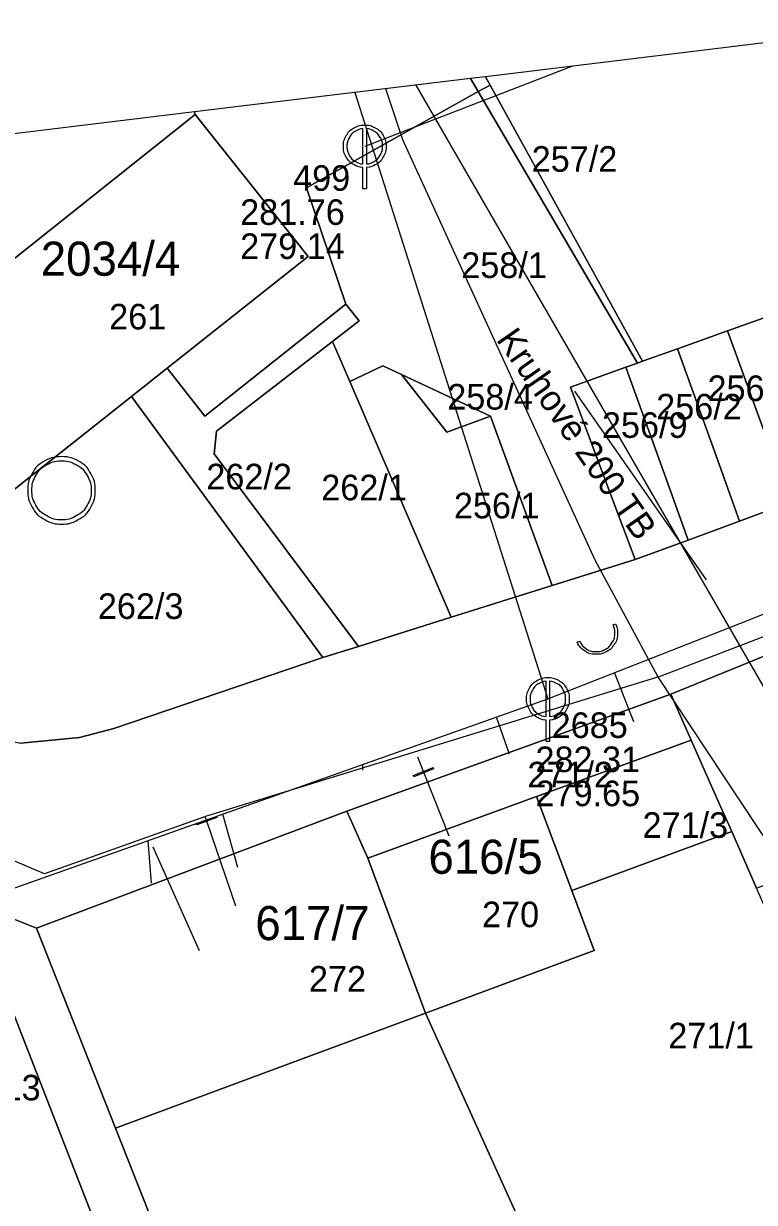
# Model space of a CAD drawing. Extents: x -571312 to -571060, y -1087128 to -1086933.
# Drawn here: x -571250.5 to -571207.6, y -1087007.2 to -1086938.1 of the extents above; entities that cross this region are included whole.
import ezdxf

# ---------------------------------------------------------------- set-up
doc = ezdxf.new("R2010")
doc.units = 0
for name, color, linetype in [('Adresní místo-text', 7, 'Continuous'), ('Armatura vodovodní', 7, 'Continuous'), ('Default', 7, 'Continuous'), ('Elektro NN - vedení', 7, 'Continuous'), ('Kanalizační přípojka', 7, 'Continuous'), ('Kanalizační stoka', 7, 'Continuous'), ('Kanalizační šachta', 7, 'Continuous'), ('Nepropojené křížení', 7, 'Continuous'), ('Parcela-polygon', 7, 'Continuous'), ('Parcela-text', 7, 'Continuous'), ('Popis kmenové stoky', 7, 'Continuous'), ('Popis šachty', 7, 'Continuous'), ('Vodovodní přípojka', 7, 'Continuous'), ('Vodovodní řad', 7, 'Continuous')]:
    doc.layers.add(name, color=color, linetype=linetype)

msp = doc.modelspace()

# ---------------------------------------------------------------- linework, layer by layer
at = {"layer": 'Armatura vodovodní'}
for points in [[(-571226.461, -1086981.776), (-571227.624, -1086982.236), (-571227.652, -1086982.163), (-571226.49, -1086981.703), (-571226.461, -1086981.776)], [(-571239.176, -1086984.632), (-571240.35, -1086985.063), (-571240.377, -1086984.989), (-571239.203, -1086984.559), (-571239.176, -1086984.632)]]:
    msp.add_lwpolyline(points, dxfattribs=at)
at = {"layer": 'Default'}
for points in [[(-571230.603, -1086946.508), (-571230.861, -1086946.49), (-571231.123, -1086946.344), (-571231.42, -1086946.18), (-571231.585, -1086945.883), (-571231.75, -1086945.585), (-571231.75, -1086945.26), (-571231.75, -1086944.933), (-571231.582, -1086944.633), (-571231.413, -1086944.332), (-571231.115, -1086944.171), (-571230.817, -1086944.01), (-571230.5, -1086944.01), (-571230.185, -1086944.01), (-571229.886, -1086944.171), (-571229.587, -1086944.332), (-571229.418, -1086944.633), (-571229.25, -1086944.933), (-571229.25, -1086945.26), (-571229.25, -1086945.585), (-571229.415, -1086945.883), (-571229.58, -1086946.18), (-571229.877, -1086946.344), (-571230.139, -1086946.49), (-571230.397, -1086946.508)], [(-571230.603, -1086944.222), (-571230.8, -1086944.239), (-571231.015, -1086944.354), (-571231.264, -1086944.489), (-571231.403, -1086944.739), (-571231.542, -1086944.989), (-571231.542, -1086945.26), (-571231.542, -1086945.531), (-571231.406, -1086945.778), (-571231.269, -1086946.024), (-571231.02, -1086946.161), (-571230.808, -1086946.281), (-571230.603, -1086946.295)], [(-571230.397, -1086946.295), (-571230.192, -1086946.281), (-571229.978, -1086946.161), (-571229.731, -1086946.024), (-571229.594, -1086945.778), (-571229.458, -1086945.531), (-571229.458, -1086945.26), (-571229.458, -1086944.989), (-571229.598, -1086944.739), (-571229.738, -1086944.489), (-571229.987, -1086944.354), (-571230.2, -1086944.239), (-571230.397, -1086944.222)], [(-571248.284, -1086963.457), (-571247.785, -1086963.457), (-571247.312, -1086963.711), (-571246.839, -1086963.966), (-571246.57, -1086964.443), (-571246.302, -1086964.92), (-571246.302, -1086965.439), (-571246.302, -1086965.952), (-571246.563, -1086966.422), (-571246.825, -1086966.892), (-571247.297, -1086967.153), (-571247.768, -1086967.415), (-571248.284, -1086967.415), (-571248.794, -1086967.415), (-571249.265, -1086967.153), (-571249.737, -1086966.892), (-571249.999, -1086966.422), (-571250.26, -1086965.952), (-571250.26, -1086965.439), (-571250.26, -1086964.92), (-571249.995, -1086964.443), (-571249.73, -1086963.966), (-571249.257, -1086963.711), (-571248.783, -1086963.457), (-571248.284, -1086963.457)], [(-571248.284, -1086963.703), (-571248.718, -1086963.703), (-571249.134, -1086963.927), (-571249.549, -1086964.15), (-571249.781, -1086964.567), (-571250.014, -1086964.984), (-571250.014, -1086965.439), (-571250.014, -1086965.887), (-571249.785, -1086966.299), (-571249.556, -1086966.711), (-571249.144, -1086966.94), (-571248.732, -1086967.169), (-571248.284, -1086967.169), (-571247.83, -1086967.169), (-571247.418, -1086966.94), (-571247.006, -1086966.711), (-571246.777, -1086966.299), (-571246.548, -1086965.887), (-571246.548, -1086965.439), (-571246.548, -1086964.984), (-571246.784, -1086964.567), (-571247.02, -1086964.15), (-571247.433, -1086963.927), (-571247.847, -1086963.703), (-571248.284, -1086963.703)], [(-571215.801, -1086973.259), (-571215.66, -1086973.553), (-571215.679, -1086973.896), (-571215.699, -1086974.239), (-571215.898, -1086974.514), (-571216.097, -1086974.789), (-571216.381, -1086974.927), (-571216.665, -1086975.064), (-571217.004, -1086975.049), (-571217.344, -1086975.034), (-571217.626, -1086974.837), (-571217.908, -1086974.64), (-571218.051, -1086974.347)], [(-571217.911, -1086974.279), (-571217.785, -1086974.536), (-571217.538, -1086974.708), (-571217.291, -1086974.88), (-571216.994, -1086974.893), (-571216.698, -1086974.906), (-571216.449, -1086974.786), (-571216.201, -1086974.666), (-571216.027, -1086974.425), (-571215.852, -1086974.184), (-571215.835, -1086973.884), (-571215.818, -1086973.585), (-571215.941, -1086973.327)], [(-571219.863, -1086978.918), (-571220.121, -1086978.9), (-571220.383, -1086978.754), (-571220.68, -1086978.59), (-571220.845, -1086978.293), (-571221.01, -1086977.995), (-571221.01, -1086977.67), (-571221.01, -1086977.343), (-571220.842, -1086977.043), (-571220.673, -1086976.742), (-571220.375, -1086976.581), (-571220.077, -1086976.42), (-571219.76, -1086976.42), (-571219.445, -1086976.42), (-571219.146, -1086976.581), (-571218.847, -1086976.742), (-571218.678, -1086977.043), (-571218.51, -1086977.343), (-571218.51, -1086977.67), (-571218.51, -1086977.995), (-571218.675, -1086978.293), (-571218.84, -1086978.59), (-571219.137, -1086978.754), (-571219.399, -1086978.9), (-571219.657, -1086978.918)], [(-571219.863, -1086976.632), (-571220.06, -1086976.649), (-571220.275, -1086976.764), (-571220.524, -1086976.899), (-571220.663, -1086977.149), (-571220.802, -1086977.399), (-571220.802, -1086977.67), (-571220.802, -1086977.941), (-571220.666, -1086978.188), (-571220.529, -1086978.434), (-571220.28, -1086978.571), (-571220.068, -1086978.691), (-571219.863, -1086978.705)], [(-571219.657, -1086978.705), (-571219.452, -1086978.691), (-571219.238, -1086978.571), (-571218.991, -1086978.434), (-571218.854, -1086978.188), (-571218.718, -1086977.941), (-571218.718, -1086977.67), (-571218.718, -1086977.399), (-571218.858, -1086977.149), (-571218.998, -1086976.899), (-571219.247, -1086976.764), (-571219.46, -1086976.649), (-571219.657, -1086976.632)]]:
    msp.add_open_spline(points, degree=3, dxfattribs=at)
at = {"layer": 'Elektro NN - vedení'}
msp.add_lwpolyline([(-571071.926, -1087014.396), (-571073.5, -1087015.707), (-571083.992, -1087003.116), (-571092.911, -1086996.034), (-571095.272, -1086994.46), (-571113.896, -1086998.657), (-571175.538, -1087035.118), (-571177.374, -1087030.659), (-571213.311, -1086976.361), (-571216.983, -1086969.541), (-571228.263, -1086944.884), (-571229.263, -1086941.883)], dxfattribs=at)
at = {"layer": 'Kanalizační přípojka'}
msp.add_line((-571240.188, -1086992.451), (-571242.9, -1086986.36), dxfattribs=at)
for points in [[(-571218.308, -1086940.555), (-571230.5, -1086945.26)], [(-571214.72, -1086979.02), (-571215.857, -1086976.12)], [(-571222.008, -1086980.907), (-571222.776, -1086978.739)], [(-571230.61, -1086981.85), (-571230.607, -1086981.513)], [(-571237.95, -1086987.56), (-571238.827, -1086984.425)], [(-571243, -1086988.48), (-571243.209, -1086985.978)]]:
    msp.add_lwpolyline(points, dxfattribs=at)
at = {"layer": 'Kanalizační stoka'}
msp.add_line((-571218.199, -1086959.617), (-571210.47, -1086970.68), dxfattribs=at)
for points in [[(-571231.086, -1086942.104), (-571228.82, -1086949.22), (-571219.76, -1086977.67)], [(-571208.5, -1086973.24), (-571194.47, -1086967.65), (-571180.44, -1086962.06)], [(-571258.91, -1086991.54), (-571219.76, -1086977.67), (-571208.5, -1086973.24)]]:
    msp.add_lwpolyline(points, dxfattribs=at)
at = {"layer": 'Kanalizační šachta'}
for points in [[(-571230.603, -1086946.295), (-571230.603, -1086944.222)], [(-571230.397, -1086944.222), (-571230.397, -1086946.295)], [(-571230.397, -1086946.508), (-571230.397, -1086947.76), (-571230.603, -1086947.76), (-571230.603, -1086946.508)], [(-571219.863, -1086978.705), (-571219.863, -1086976.632)], [(-571219.657, -1086976.632), (-571219.657, -1086978.705)], [(-571219.657, -1086978.918), (-571219.657, -1086980.17), (-571219.863, -1086980.17), (-571219.863, -1086978.918)]]:
    msp.add_lwpolyline(points, dxfattribs=at)
at = {"layer": 'Nepropojené křížení'}
for points in [[(-571215.941, -1086973.327), (-571215.801, -1086973.259)], [(-571218.051, -1086974.347), (-571217.911, -1086974.279)]]:
    msp.add_lwpolyline(points, dxfattribs=at)
at = {"layer": 'Parcela-polygon'}
for p, q in [((-571197.723, -1086938.059), (-571223.423, -1086941.175)), ((-571224.291, -1086941.28), (-571240.477, -1086943.242)), ((-571223.423, -1086941.175), (-571224.291, -1086941.28)), ((-571240.477, -1086943.242), (-571288.74, -1086949.093))]:
    msp.add_line(p, q, dxfattribs=at)
for points in [[(-571223.423, -1086941.175), (-571223.15, -1086941.67), (-571214.21, -1086957.87), (-571212.16, -1086957.14), (-571209.22, -1086956.09), (-571206.25, -1086955.03), (-571203.34, -1086954), (-571200.29, -1086952.91), (-571197.31, -1086951.84), (-571194.02, -1086950.67), (-571193.73, -1086950.56), (-571197.723, -1086938.059)], [(-571240.477, -1086943.242), (-571240.45, -1086943.4), (-571233.81, -1086951.73), (-571242.08, -1086958.27), (-571239.88, -1086961.08), (-571231.6, -1086954.52), (-571233.92, -1086947.7), (-571223.84, -1086942.05), (-571224.291, -1086941.28)], [(-571224.291, -1086941.28), (-571223.84, -1086942.05), (-571223.15, -1086941.67), (-571223.423, -1086941.175)], [(-571288.74, -1086949.093), (-571266.82, -1086964.63), (-571258.55, -1086957.8), (-571240.45, -1086943.4), (-571240.477, -1086943.242)], [(-571152.86, -1086947.07), (-571155.22, -1086947.92), (-571190.51, -1086960.64), (-571193.66, -1086961.8), (-571196.64, -1086962.89), (-571199.6, -1086963.98), (-571202.6, -1086965.08), (-571205.57, -1086966.16), (-571208.52, -1086967.25), (-571211.54, -1086968.35), (-571214.64, -1086969.49), (-571219.5, -1086971.02), (-571225.44, -1086972.88), (-571230.87, -1086974.59), (-571232.95, -1086975.24), (-571245.21, -1086979.4), (-571247.22, -1086979.94), (-571250.67, -1086980.27)], [(-571308.971, -1086951.546), (-571306.25, -1086957.27), (-571289.46, -1086969.43), (-571269.48, -1086983.31), (-571253.67, -1086989.56), (-571249.74, -1086991.11), (-571231.55, -1086984.26), (-571212.55, -1086977.39), (-571191.88, -1086968.96), (-571178.41, -1086963.67), (-571168.71, -1086959.87), (-571150.45, -1086953.94)]]:
    msp.add_lwpolyline(points, dxfattribs=at)
for points in [[(-571231.6, -1086954.52), (-571230.83, -1086955.5), (-571232.39, -1086956.71), (-571231.38, -1086959.05), (-571229.43, -1086958.13), (-571228.35, -1086958.64), (-571223.13, -1086961.09), (-571219.5, -1086971.02), (-571214.64, -1086969.49), (-571216.1, -1086965.61), (-571218.44, -1086959.38), (-571215.18, -1086958.22), (-571214.51, -1086957.98), (-571223.84, -1086942.05), (-571233.92, -1086947.7)], [(-571223.15, -1086941.67), (-571223.84, -1086942.05), (-571214.51, -1086957.98), (-571214.21, -1086957.87)], [(-571240.45, -1086943.4), (-571258.55, -1086957.8), (-571252.01, -1086966.13), (-571244.18, -1086959.93), (-571242.08, -1086958.27), (-571233.81, -1086951.73)], [(-571232.95, -1086975.24), (-571230.87, -1086974.59), (-571239.34, -1086963.29), (-571239.2, -1086961.96), (-571232.39, -1086956.71), (-571230.83, -1086955.5), (-571231.6, -1086954.52), (-571239.88, -1086961.08), (-571242.08, -1086958.27), (-571244.18, -1086959.93)], [(-571209.22, -1086956.09), (-571206.94, -1086962.36), (-571205.57, -1086966.16), (-571202.6, -1086965.08), (-571203.97, -1086961.31), (-571206.25, -1086955.03)], [(-571212.16, -1086957.14), (-571209.9, -1086963.41), (-571208.52, -1086967.25), (-571205.57, -1086966.16), (-571206.94, -1086962.36), (-571209.22, -1086956.09)], [(-571230.87, -1086974.59), (-571225.44, -1086972.88), (-571231.38, -1086959.05), (-571232.39, -1086956.71), (-571239.2, -1086961.96), (-571239.34, -1086963.29)], [(-571215.18, -1086958.22), (-571212.93, -1086964.48), (-571211.54, -1086968.35), (-571208.52, -1086967.25), (-571209.9, -1086963.41), (-571212.16, -1086957.14), (-571214.21, -1086957.87), (-571214.51, -1086957.98)], [(-571219.5, -1086971.02), (-571223.13, -1086961.09), (-571225.68, -1086962.02), (-571228.35, -1086958.64), (-571229.43, -1086958.13), (-571231.38, -1086959.05), (-571225.44, -1086972.88)], [(-571218.44, -1086959.38), (-571216.1, -1086965.61), (-571214.64, -1086969.49), (-571211.54, -1086968.35), (-571212.93, -1086964.48), (-571215.18, -1086958.22)], [(-571223.13, -1086961.09), (-571228.35, -1086958.64), (-571225.68, -1086962.02)], [(-571252.01, -1086966.13), (-571263.43, -1086975.32), (-571260.26, -1086977.58), (-571257.91, -1086978.43), (-571254.71, -1086979.53), (-571250.67, -1086980.27), (-571247.22, -1086979.94), (-571245.21, -1086979.4), (-571232.95, -1086975.24), (-571244.18, -1086959.93)], [(-571191.88, -1086968.96), (-571212.55, -1086977.39), (-571211.36, -1086980.09), (-571209.71, -1086983.81), (-571208.98, -1086985.45), (-571207.52, -1086988.77), (-571203.45, -1086987.16), (-571196.09, -1086984.48), (-571187.29, -1086981.31), (-571190.63, -1086972.39)], [(-571231.55, -1086984.26), (-571230.31, -1086987.01), (-571220.43, -1086983.4), (-571211.36, -1086980.09), (-571212.55, -1086977.39)], [(-571211.36, -1086980.09), (-571220.43, -1086983.4), (-571218.36, -1086988.9), (-571208.98, -1086985.45), (-571209.71, -1086983.81)], [(-571230.31, -1086987.01), (-571226.94, -1086996.1), (-571217.04, -1086992.42), (-571218.36, -1086988.9), (-571220.43, -1086983.4)], [(-571230.31, -1086987.01), (-571231.55, -1086984.26), (-571249.74, -1086991.11), (-571245.11, -1087002.85), (-571236.54, -1086999.66), (-571226.94, -1086996.1)], [(-571208.98, -1086985.45), (-571218.36, -1086988.9), (-571217.04, -1086992.42), (-571226.94, -1086996.1), (-571217.97, -1087015.93), (-571206.82, -1087010.23), (-571199.65, -1087006.57), (-571207.52, -1086988.77)], [(-571223.27, -1087054.35), (-571220.52, -1087052.71), (-571221.22, -1087051.48), (-571224.28, -1087046.14), (-571236.3, -1087025.16), (-571245.11, -1087002.85), (-571249.74, -1086991.11), (-571253.67, -1086989.56), (-571252.89, -1086991.54), (-571239.35, -1087026.31), (-571236.49, -1087031.3)], [(-571280.58, -1087024.78), (-571275.83, -1087028.1), (-571251.17, -1087045.35), (-571243.07, -1087038.57), (-571255.12, -1087027.8), (-571244.8, -1087016.38), (-571238.33, -1087033.34), (-571236.49, -1087031.3), (-571239.35, -1087026.31), (-571252.89, -1086991.54), (-571254.35, -1086990.89), (-571254.9, -1086994.13), (-571258.67, -1087000.06), (-571285.9, -1087020.87), (-571280.44, -1087024.63)], [(-571226.94, -1086996.1), (-571236.54, -1086999.66), (-571245.11, -1087002.85), (-571236.3, -1087025.16), (-571222.72, -1087018.32), (-571217.97, -1087015.93)]]:
    msp.add_lwpolyline(points, close=True, dxfattribs=at)
at = {"layer": 'Vodovodní přípojka'}
msp.add_line((-571227.41, -1086981.075), (-571225.577, -1086985.71), dxfattribs=at)
msp.add_lwpolyline([(-571238.061, -1086989.819), (-571239.786, -1086984.781), (-571239.856, -1086984.577)], dxfattribs=at)
at = {"layer": 'Vodovodní řad'}
for points in [[(-571259.706, -1087078.885), (-571257.725, -1087077.417), (-571211.542, -1087050.048), (-571176.933, -1087029.184), (-571227.483, -1086941.667)], [(-571118.52, -1087001.2), (-571118.67, -1087000.053), (-571123.745, -1086988.554), (-571132.766, -1086954.96), (-571134.366, -1086951.47), (-571139.458, -1086950.161), (-571144.547, -1086950.9), (-571169.366, -1086958.786), (-571197.91, -1086970.492), (-571213.143, -1086976.341), (-571239.84, -1086984.572), (-571249.273, -1086987.925), (-571267.719, -1086980.097), (-571298.302, -1086956.821), (-571302.312, -1086953.213), (-571303.56, -1086950.89)]]:
    msp.add_lwpolyline(points, dxfattribs=at)

# ---------------------------------------------------------------- texts
at = {"layer": 'Adresní místo-text'}
for s, p in [('2034/4', (-571249.501, -1086952.85)), ('616/5', (-571226.765, -1086987.93)), ('617/7', (-571236.915, -1086991.82))]:
    msp.add_text(s, height=2, dxfattribs=at).set_placement(p)
at = {"layer": 'Parcela-text'}
for s, p in [('257/2', (-571220.71, -1086946.75)), ('258/1', (-571224.84, -1086952.98)), ('261', (-571245.49, -1086956)), ('256/3', (-571210.4, -1086960.2)), ('258/4', (-571225.66, -1086960.7)), ('256/2', (-571213.41, -1086961.28)), ('256/9', (-571216.59, -1086962.36)), ('262/2', (-571239.79, -1086965.38)), ('262/1', (-571233.05, -1086966.02)), ('256/1', (-571225.27, -1086967.08)), ('262/3', (-571246.15, -1086972.98)), ('271/2', (-571220.96, -1086982.86)), ('271/3', (-571214.21, -1086985.82)), ('270', (-571223.62, -1086991.06)), ('272', (-571233.77, -1086994.84)), ('271/1', (-571212.7, -1086998.17)), ('322/13', (-571255.64, -1087001.22))]:
    msp.add_text(s, height=1.5, dxfattribs=at).set_placement(p)
at = {"layer": 'Popis kmenové stoky'}
msp.add_text('Kruhové 200 TB', height=1.5, rotation=304.93948, dxfattribs=at).set_placement((-571222.829, -1086956.599))
at = {"layer": 'Popis šachty'}
for s, p in [('499', (-571234.699, -1086947.867)), ('281.76', (-571237.806, -1086949.867)), ('279.14', (-571237.806, -1086951.867)), ('2685', (-571219.539, -1086979.963)), ('282.31', (-571220.488, -1086981.963)), ('279.65', (-571220.488, -1086983.963))]:
    msp.add_text(s, height=1.5, dxfattribs=at).set_placement(p)

doc.saveas('drawing.dxf')
